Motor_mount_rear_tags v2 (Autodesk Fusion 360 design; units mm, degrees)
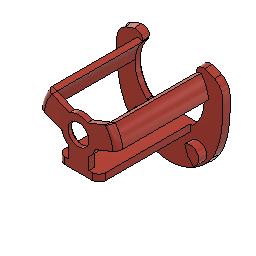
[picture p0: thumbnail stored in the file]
base_feature "Base Feature2"
base_feature "Base Feature1"
work_plane "WorkPlane1" AlongDistance -50.1
sketch "Sketch3" plane through (0, 0, -50.1) normal (0, 0, 1) x axis (1, 0, 0)
extrude "Extrude1" new body sketch "Sketch3" along normal blind 2 taper -5
sketch "Sketch12" plane through (0, 0, -48.1) normal (0, 0, 1) x axis (1, 0, 0)
extrude "Extrude9" cut sketch "Sketch12" no distance stored
sketch "Sketch13" plane through (0, 0, -48.1) normal (0, 0, 1) x axis (1, 0, 0)
  dimension "d100" = 2
  dimension "d104" = 1.5
  dimension "d105" = 6
  dimension "d106" = 12
extrude "Extrude10" add sketch "Sketch13" along normal blind 25
sketch "Sketch14" plane through (0, 0, -23.1) normal (0, 0, 1) x axis (1, 0, 0)
  dimension "d109" = 6.0836
  dimension "d110" = 10
extrude "Extrude11" add sketch "Sketch14" along normal blind 1.5
sketch "Sketch7" plane through (0, 0, -48.1) normal (0, 0, 1) x axis (1, 0, 0)
  dimension "d141" = 4
  dimension "d143" = 4
  dimension "d144" = 2.5
  dimension "d113" = 2
  dimension "d114" = 8
extrude "Extrude5" add sketch "Sketch7" along normal blind 2.5
fillet "Fillet2" radius 1
sketch "Sketch8" plane through (4.0871, 0, 0) normal (1, 0, 0) x axis (0, 0, -1)
sketch "Sketch9" plane through (4.0871, 0, 0) normal (1, 0, 0) x axis (0, 0, -1)
  dimension "d148" = 0.4
  dimension "d149" = 0.8
extrude "Extrude6" cut sketch "Sketch9" to an object
sketch "Sketch10" plane through (0, 0, -48.1) normal (0, 0, 1) x axis (1, 0, 0)
  dimension "d154" = 29.9506
  dimension "d155" = 26.0609
  dimension "d161" = 2.5
  dimension "d162" = 3.5
extrude "Extrude7" add sketch "Sketch10" along normal blind 0.8
sketch "Sketch11" plane through (0, 0, -47.3) normal (0, 0, 1) x axis (1, 0, 0)
  dimension "d164" = 1
extrude "Extrude8" add sketch "Sketch11" along normal blind 1.5
fillet "Fillet3" radius 2
chamfer "Chamfer2" distance 0.5
fillet "Fillet4" radius 1.5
